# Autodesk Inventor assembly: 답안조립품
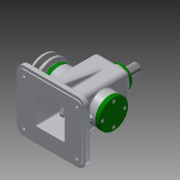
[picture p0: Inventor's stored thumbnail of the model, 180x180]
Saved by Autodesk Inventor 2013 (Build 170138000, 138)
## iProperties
Created: 2016-01
Part Number: 답안조립품
Document SubType Name: Assembly
Designer: User
Author: User
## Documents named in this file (14)
- C:\Users\User\Desktop\460126V1008\답안조립품.iam
- C:\Users\User\Desktop\460126V1008\본체.ipt
- C:\Users\User\Desktop\460126V1008\앞커버.ipt
- C:\Users\User\Desktop\460126V1008\뒤커버.ipt
- C:\Users\User\Desktop\460126V1008\볼트 M4 x 10.ipt
- C:\Users\User\Desktop\460126V1008\상부부시.ipt
- C:\Users\User\Desktop\460126V1008\볼트 M3 x 8.ipt
- C:\Users\User\Desktop\460126V1008\베어링 15 x 35 x 11.ipt
- C:\Users\User\Desktop\460126V1008\편심축.ipt
- C:\Users\User\Desktop\460126V1008\멈춤링 15 x 1.ipt
- C:\Users\User\Desktop\460126V1008\키 5 x 5 x 14.ipt
- C:\Users\User\Desktop\460126V1008\V-벨트풀리.ipt
- C:\Users\User\Desktop\460126V1008\슬라이드바.ipt
- C:\Users\User\Desktop\460126V1008\링크.ipt
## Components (13 placed, 3 different names)
1. V-벨트풀리:1
2. ISO 4762 M4 x 10:2
3. ISO 4762 M4 x 10:3
4. ISO 4762 M4 x 10:4
5. ISO 4762 M4 x 10:5
6. ISO 4762 M4 x 10:1
7. ISO 4762 M4 x 10:6
8. ISO 4762 M4 x 10:7
9. ISO 4762 M4 x 10:8
10. ISO 4762 M3 x 8:1
11. ISO 4762 M3 x 8:2
12. ISO 4762 M3 x 8:3
13. ISO 4762 M3 x 8:4
